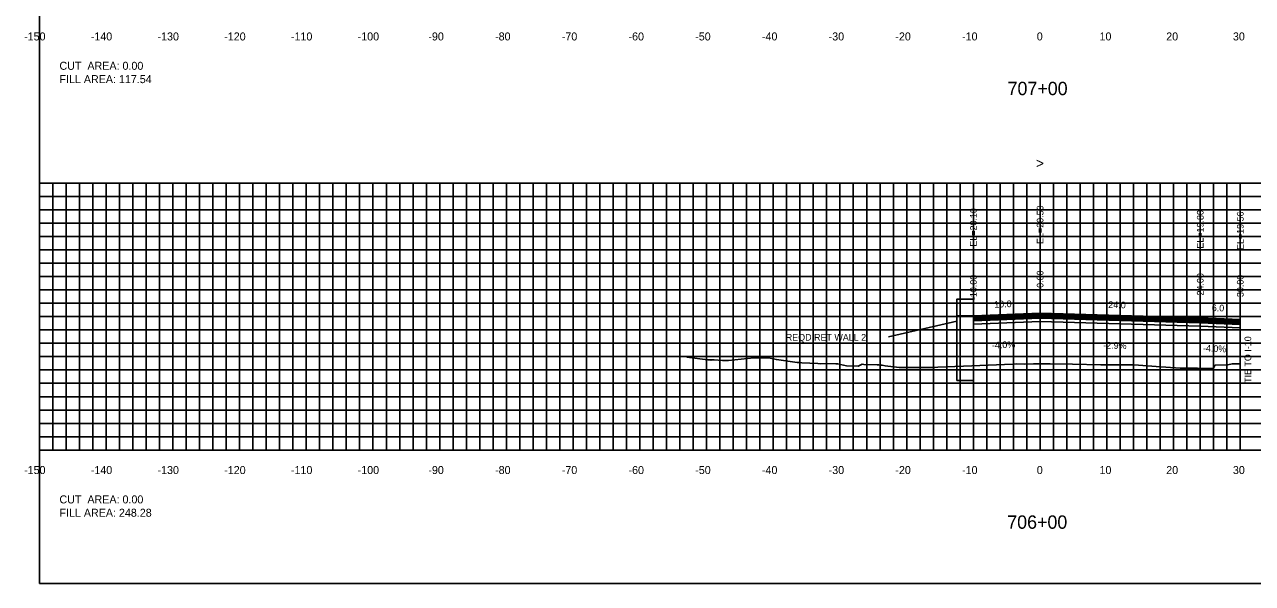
# Model space of a CAD drawing. Extents: x 1797518 to 1804843, y 248068 to 251132.
# Drawn here: x 1803838.8 to 1804022.8, y 250079.4 to 250163.2 of the extents above; entities that cross this region are included whole.
import ezdxf

# ---------------------------------------------------------------- set-up
doc = ezdxf.new("R2010")
doc.units = 0
for name, color, linetype in [('1', 7, 'Continuous'), ('10', 7, 'Continuous'), ('3', 7, 'Continuous'), ('4', 7, 'Continuous'), ('60', 7, 'Continuous'), ('ANNO-TXT', 7, 'Continuous'), ('BASE', 7, 'Continuous'), ('CL-CNST', 7, 'Continuous'), ('Level 62', 7, 'Continuous'), ('LOWER BINDER', 7, 'Continuous'), ('M-ROADS', 7, 'Continuous'), ('UPPER BINDER', 7, 'Continuous'), ('WEARING', 7, 'Continuous')]:
    doc.layers.add(name, color=color, linetype=linetype)

msp = doc.modelspace()

# ---------------------------------------------------------------- linework, layer by layer
for p, q in [((1803981, 250119.53), (1803981, 250121.53)), ((1803991, 250119.93), (1803991, 250121.93)), ((1804015, 250119.23), (1804015, 250121.23)), ((1804021, 250118.99), (1804021, 250120.99))]:
    msp.add_line(p, q)
msp.add_lwpolyline([(1803841, 250079.43), (1804141, 250079.43), (1804141, 250269.43), (1803841, 250269.43)], close=True)
at = {"layer": '3'}
for p, q in [((1804021, 250120.08), (1804021, 250110.05)), ((1804021, 250119.74), (1804021, 250109.72)), ((1803968.28, 250116.38), (1803978.5, 250118.77))]:
    msp.add_line(p, q, dxfattribs=at)
at = {"layer": '60'}
for p, q in [((1803840.94, 250139.43), (1803841, 250139.43)), ((1803841, 250099.43), (1803841, 250139.43)), ((1803840.94, 250129.43), (1803841, 250129.43)), ((1803840.94, 250119.43), (1803841, 250119.43)), ((1803840.94, 250109.43), (1803841, 250109.43)), ((1803840.94, 250099.43), (1803841, 250099.43)), ((1803841, 250099.43), (1804141, 250099.43)), ((1803841, 250099.37), (1803841, 250099.43)), ((1803851, 250099.37), (1803851, 250099.43)), ((1803861, 250099.37), (1803861, 250099.43)), ((1803871, 250099.37), (1803871, 250099.43)), ((1803881, 250099.37), (1803881, 250099.43)), ((1803891, 250099.37), (1803891, 250099.43)), ((1803901, 250099.37), (1803901, 250099.43)), ((1803911, 250099.37), (1803911, 250099.43)), ((1803921, 250099.37), (1803921, 250099.43)), ((1803931, 250099.37), (1803931, 250099.43)), ((1803941, 250099.37), (1803941, 250099.43)), ((1803951, 250099.37), (1803951, 250099.43)), ((1803961, 250099.37), (1803961, 250099.43)), ((1803971, 250099.37), (1803971, 250099.43)), ((1803981, 250099.37), (1803981, 250099.43)), ((1803991, 250099.37), (1803991, 250099.43)), ((1804001, 250099.37), (1804001, 250099.43)), ((1804011, 250099.37), (1804011, 250099.43)), ((1804021, 250099.37), (1804021, 250099.43))]:
    msp.add_line(p, q, dxfattribs=at)
at = {"layer": 'BASE'}
msp.add_lwpolyline([(1803981, 250118.81), (1803991, 250119.21), (1804015, 250118.51), (1804021, 250118.27), (1804021, 250117.77), (1804015, 250118.01), (1803991, 250118.71), (1803981, 250118.31)], close=True, dxfattribs=at)
at = {"layer": 'CL-CNST'}
for points in [[(1803981, 250119.53), (1803978.5, 250119.53), (1803978.5, 250122.03), (1803981, 250122.03)], [(1803978.5, 250109.87), (1803981, 250109.87), (1803981, 250119.53), (1803978.5, 250119.53)]]:
    msp.add_lwpolyline(points, close=True, dxfattribs=at)
msp.add_lwpolyline([(1803981, 250119.53), (1803991, 250119.93), (1804015, 250119.23), (1804021, 250118.99)], dxfattribs=at)
at = {"layer": 'Level 62'}
for p, q in [((1803841, 250139.43), (1804141, 250139.43)), ((1803841, 250099.43), (1803841, 250139.43)), ((1803843, 250099.43), (1803843, 250139.43)), ((1803845, 250099.43), (1803845, 250139.43)), ((1803847, 250099.43), (1803847, 250139.43)), ((1803849, 250099.43), (1803849, 250139.43)), ((1803851, 250099.43), (1803851, 250139.43)), ((1803853, 250099.43), (1803853, 250139.43)), ((1803855, 250099.43), (1803855, 250139.43)), ((1803857, 250099.43), (1803857, 250139.43)), ((1803859, 250099.43), (1803859, 250139.43)), ((1803861, 250099.43), (1803861, 250139.43)), ((1803863, 250099.43), (1803863, 250139.43)), ((1803865, 250099.43), (1803865, 250139.43)), ((1803867, 250099.43), (1803867, 250139.43)), ((1803869, 250099.43), (1803869, 250139.43)), ((1803871, 250099.43), (1803871, 250139.43)), ((1803873, 250099.43), (1803873, 250139.43)), ((1803875, 250099.43), (1803875, 250139.43)), ((1803877, 250099.43), (1803877, 250139.43)), ((1803879, 250099.43), (1803879, 250139.43)), ((1803881, 250099.43), (1803881, 250139.43)), ((1803883, 250099.43), (1803883, 250139.43)), ((1803885, 250099.43), (1803885, 250139.43)), ((1803887, 250099.43), (1803887, 250139.43)), ((1803889, 250099.43), (1803889, 250139.43)), ((1803891, 250099.43), (1803891, 250139.43)), ((1803893, 250099.43), (1803893, 250139.43)), ((1803895, 250099.43), (1803895, 250139.43)), ((1803897, 250099.43), (1803897, 250139.43)), ((1803899, 250099.43), (1803899, 250139.43)), ((1803901, 250099.43), (1803901, 250139.43)), ((1803903, 250099.43), (1803903, 250139.43)), ((1803905, 250099.43), (1803905, 250139.43)), ((1803907, 250099.43), (1803907, 250139.43)), ((1803909, 250099.43), (1803909, 250139.43)), ((1803911, 250099.43), (1803911, 250139.43)), ((1803913, 250099.43), (1803913, 250139.43)), ((1803915, 250099.43), (1803915, 250139.43)), ((1803917, 250099.43), (1803917, 250139.43)), ((1803919, 250099.43), (1803919, 250139.43)), ((1803921, 250099.43), (1803921, 250139.43)), ((1803923, 250099.43), (1803923, 250139.43)), ((1803925, 250099.43), (1803925, 250139.43)), ((1803927, 250099.43), (1803927, 250139.43)), ((1803929, 250099.43), (1803929, 250139.43)), ((1803931, 250099.43), (1803931, 250139.43)), ((1803933, 250099.43), (1803933, 250139.43)), ((1803935, 250099.43), (1803935, 250139.43)), ((1803937, 250099.43), (1803937, 250139.43)), ((1803939, 250099.43), (1803939, 250139.43)), ((1803941, 250099.43), (1803941, 250139.43)), ((1803943, 250099.43), (1803943, 250139.43)), ((1803945, 250099.43), (1803945, 250139.43)), ((1803947, 250099.43), (1803947, 250139.43)), ((1803949, 250099.43), (1803949, 250139.43)), ((1803951, 250099.43), (1803951, 250139.43)), ((1803953, 250099.43), (1803953, 250139.43)), ((1803955, 250099.43), (1803955, 250139.43)), ((1803957, 250099.43), (1803957, 250139.43)), ((1803959, 250099.43), (1803959, 250139.43)), ((1803961, 250099.43), (1803961, 250139.43)), ((1803963, 250099.43), (1803963, 250139.43)), ((1803965, 250099.43), (1803965, 250139.43)), ((1803967, 250099.43), (1803967, 250139.43)), ((1803969, 250099.43), (1803969, 250139.43)), ((1803971, 250099.43), (1803971, 250139.43)), ((1803973, 250099.43), (1803973, 250139.43)), ((1803975, 250099.43), (1803975, 250139.43)), ((1803977, 250099.43), (1803977, 250139.43)), ((1803979, 250099.43), (1803979, 250139.43)), ((1803981, 250099.43), (1803981, 250139.43)), ((1803983, 250099.43), (1803983, 250139.43)), ((1803985, 250099.43), (1803985, 250139.43)), ((1803987, 250099.43), (1803987, 250139.43)), ((1803989, 250099.43), (1803989, 250139.43)), ((1803991, 250099.43), (1803991, 250139.43)), ((1803993, 250099.43), (1803993, 250139.43)), ((1803995, 250099.43), (1803995, 250139.43)), ((1803997, 250099.43), (1803997, 250139.43)), ((1803999, 250099.43), (1803999, 250139.43)), ((1804001, 250099.43), (1804001, 250139.43)), ((1804003, 250099.43), (1804003, 250139.43)), ((1804005, 250099.43), (1804005, 250139.43)), ((1804007, 250099.43), (1804007, 250139.43)), ((1804009, 250099.43), (1804009, 250139.43)), ((1804011, 250099.43), (1804011, 250139.43)), ((1804013, 250099.43), (1804013, 250139.43)), ((1804015, 250099.43), (1804015, 250139.43)), ((1804017, 250099.43), (1804017, 250139.43)), ((1804019, 250099.43), (1804019, 250139.43)), ((1804021, 250099.43), (1804021, 250139.43)), ((1803841, 250137.43), (1804141, 250137.43)), ((1803841, 250135.43), (1804141, 250135.43)), ((1803841, 250133.43), (1804141, 250133.43)), ((1803841, 250131.43), (1804141, 250131.43)), ((1803841, 250129.43), (1804141, 250129.43)), ((1803841, 250127.43), (1804141, 250127.43)), ((1803841, 250125.43), (1804141, 250125.43)), ((1803841, 250123.43), (1804141, 250123.43)), ((1803841, 250121.43), (1804141, 250121.43)), ((1803841, 250119.43), (1804141, 250119.43)), ((1803841, 250117.43), (1804141, 250117.43)), ((1803841, 250115.43), (1804141, 250115.43)), ((1803841, 250113.43), (1804141, 250113.43)), ((1803841, 250111.43), (1804141, 250111.43)), ((1803841, 250109.43), (1804141, 250109.43)), ((1803841, 250107.43), (1804141, 250107.43)), ((1803841, 250105.43), (1804141, 250105.43)), ((1803841, 250103.43), (1804141, 250103.43)), ((1803841, 250101.43), (1804141, 250101.43)), ((1803841, 250099.43), (1804141, 250099.43))]:
    msp.add_line(p, q, dxfattribs=at)
at = {"layer": 'LOWER BINDER'}
for points in [[(1803991, 250119.59), (1804015, 250118.89), (1804021, 250118.65), (1804021, 250118.46), (1804015, 250118.7), (1803991, 250119.4), (1803981, 250119), (1803981, 250119.19)], [(1803991, 250119.4), (1804015, 250118.7), (1804021, 250118.46), (1804021, 250118.27), (1804015, 250118.51), (1803991, 250119.21), (1803981, 250118.81), (1803981, 250119)]]:
    msp.add_lwpolyline(points, close=True, dxfattribs=at)
at = {"layer": 'M-ROADS'}
msp.add_lwpolyline([(1803938.06, 250113.35), (1803941.21, 250112.93), (1803941.6, 250112.94), (1803941.67, 250112.9), (1803941.68, 250112.93), (1803942.15, 250112.93), (1803943.41, 250112.87), (1803943.89, 250112.87), (1803944.02, 250112.84), (1803944.27, 250112.86), (1803947.15, 250113.15), (1803948.07, 250113.25), (1803949.25, 250113.25), (1803950.3, 250113.25), (1803951.46, 250112.98), (1803954.59, 250112.56), (1803955.01, 250112.56), (1803955.26, 250112.52), (1803957.68, 250112.42), (1803958.06, 250112.37), (1803959.09, 250112.42), (1803960.38, 250112.33), (1803960.65, 250112.36), (1803961.99, 250112.05), (1803963.72, 250112.02), (1803963.85, 250112.05), (1803964.3, 250112.28), (1803964.58, 250112.24), (1803966.56, 250112.22), (1803966.62, 250112.18), (1803966.66, 250112.22), (1803966.67, 250112.21), (1803966.68, 250112.22), (1803966.79, 250112.22), (1803967.15, 250112.15), (1803967.34, 250112.13), (1803967.77, 250112.07), (1803969.85, 250111.81), (1803969.9, 250111.81), (1803969.99, 250111.8), (1803970.32, 250111.8), (1803972.43, 250111.8), (1803974.04, 250111.8), (1803974.91, 250111.8), (1803975.24, 250111.82), (1803975.68, 250111.83), (1803979.51, 250111.99), (1803986.91, 250112.31), (1803987.49, 250112.34), (1803988.71, 250112.32), (1803990.01, 250112.33), (1803990.14, 250112.33), (1803992.5, 250112.33), (1803995.83, 250112.28), (1804000.08, 250112.21), (1804002.17, 250112.21), (1804002.58, 250112.21), (1804003.72, 250112.2), (1804005.09, 250112.21), (1804008.41, 250111.95), (1804012, 250111.69), (1804013.24, 250111.7), (1804014.52, 250111.68), (1804014.62, 250111.67), (1804016.74, 250111.66), (1804017.01, 250111.7), (1804017.19, 250112.15), (1804019.13, 250112.18), (1804019.77, 250112.33), (1804021, 250112.33)], dxfattribs=at)
at = {"layer": 'UPPER BINDER'}
msp.add_lwpolyline([(1804021, 250118.65), (1804021, 250118.84), (1804015, 250119.08), (1803991, 250119.78), (1803981, 250119.38), (1803981, 250119.19), (1803991, 250119.59), (1804015, 250118.89)], close=True, dxfattribs=at)
at = {"layer": 'WEARING'}
msp.add_lwpolyline([(1804021, 250118.84), (1804021, 250118.99), (1804015, 250119.23), (1803991, 250119.93), (1803981, 250119.53), (1803981, 250119.38), (1803991, 250119.78), (1804015, 250119.08)], close=True, dxfattribs=at)

# ---------------------------------------------------------------- texts
at = {"layer": '1'}
for s, p in [('707+00', (1803986.12, 250152.63)), ('706+00', (1803986.07, 250087.63))]:
    msp.add_text(s, height=2, dxfattribs=at).set_placement(p)
at = {"layer": '10'}
for s, p in [('-150', (1803838.7, 250160.83)), ('-140', (1803848.7, 250160.83)), ('-130', (1803858.7, 250160.83)), ('-120', (1803868.7, 250160.83)), ('-110', (1803878.7, 250160.83)), ('-100', (1803888.7, 250160.83)), ('-90', (1803899.3, 250160.83)), ('-80', (1803909.3, 250160.83)), ('-70', (1803919.3, 250160.83)), ('-60', (1803929.3, 250160.83)), ('-50', (1803939.3, 250160.83)), ('-40', (1803949.3, 250160.83)), ('-30', (1803959.3, 250160.83)), ('-20', (1803969.3, 250160.83)), ('-10', (1803979.3, 250160.83)), ('0', (1803990.5, 250160.83)), ('10', (1803999.9, 250160.83)), ('20', (1804009.9, 250160.83)), ('30', (1804019.9, 250160.83)), ('-150', (1803838.7, 250095.83)), ('-140', (1803848.7, 250095.83)), ('-130', (1803858.7, 250095.83)), ('-120', (1803868.7, 250095.83)), ('-110', (1803878.7, 250095.83)), ('-100', (1803888.7, 250095.83)), ('-90', (1803899.3, 250095.83)), ('-80', (1803909.3, 250095.83)), ('-70', (1803919.3, 250095.83)), ('-60', (1803929.3, 250095.83)), ('-50', (1803939.3, 250095.83)), ('-40', (1803949.3, 250095.83)), ('-30', (1803959.3, 250095.83)), ('-20', (1803969.3, 250095.83)), ('-10', (1803979.3, 250095.83)), ('0', (1803990.5, 250095.83)), ('10', (1803999.9, 250095.83)), ('20', (1804009.9, 250095.83)), ('30', (1804019.9, 250095.83))]:
    msp.add_text(s, height=1.2, dxfattribs=at).set_placement(p)
at = {"layer": '3'}
for s, p in [('EL=20.50', (1803991.5, 250130.33)), ('EL=20.10', (1803981.5, 250129.93)), ('EL=19.80', (1804015.5, 250129.63)), ('EL=19.56', (1804021.5, 250129.42)), ('-10.00', (1803981.5, 250121.91)), ('-0.00', (1803991.5, 250123.3)), ('24.00', (1804015.5, 250122.6)), ('30.00', (1804021.5, 250122.36)), ('TIE TO I-10', (1804022.64, 250109.49))]:
    msp.add_text(s, height=1, rotation=90, dxfattribs=at).set_placement(p)
msp.add_text('REQD RET WALL 2', height=1, dxfattribs=at).set_placement((1803952.88, 250115.83))
at = {"layer": '4'}
for s, rotation, p in [('10.0', 2.2906, (1803984.14, 250120.76)), ('24.0', 358.3274, (1804001.22, 250120.74)), ('6.0', 357.7094, (1804016.72, 250120.27)), ('-4.0%', 2.2906, (1803983.79, 250114.64)), ('-2.9%', 358.3274, (1804000.45, 250114.66)), ('-4.0%', 357.7094, (1804015.39, 250114.21))]:
    msp.add_text(s, height=1, rotation=rotation, dxfattribs=at).set_placement(p)
at = {"layer": '60'}
for s, height, p in [('>', 1.5, (1803990.39, 250141.68)), ('-', 0.0001, (1803841, 250099.43))]:
    msp.add_text(s, height=height, dxfattribs=at).set_placement(p)
at = {"layer": 'ANNO-TXT'}
for s, p in [('CUT  AREA: 0.00', (1803844, 250156.43)), ('FILL AREA: 117.54', (1803844, 250154.43)), ('CUT  AREA: 0.00', (1803844, 250091.43)), ('FILL AREA: 248.28', (1803844, 250089.43))]:
    msp.add_text(s, height=1.2, dxfattribs=at).set_placement(p)

doc.saveas('drawing.dxf')
